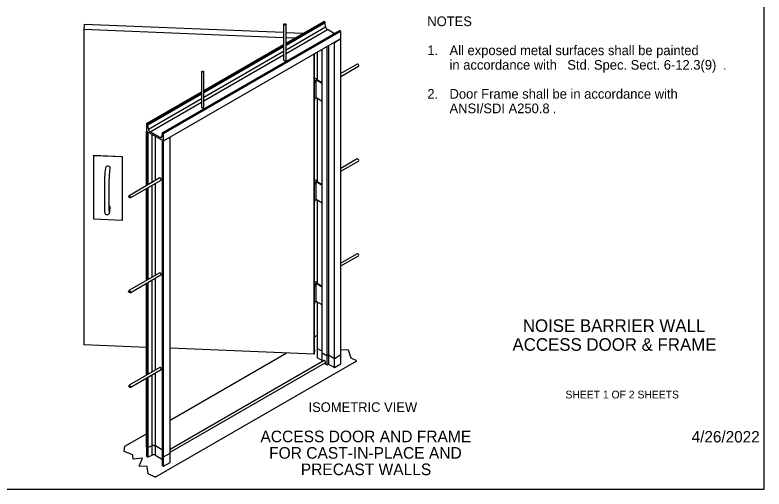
# Model space of a CAD drawing. Extents: x 99862 to 103151, y 100000 to 105076.
# Drawn here: x 101604 to 103151, y 100000 to 100979 of the extents above; entities that cross this region are included whole.
import ezdxf

# ---------------------------------------------------------------- set-up
doc = ezdxf.new("R2010")
doc.units = 0
for name, color, linetype in [('Level 1', 7, 'Continuous'), ('Level 15', 7, 'Continuous'), ('Level 18', 7, 'Continuous'), ('Level 20', 7, 'Continuous'), ('Level 5', 7, 'Continuous'), ('Level 62', 7, 'Continuous')]:
    doc.layers.add(name, color=color, linetype=linetype)

msp = doc.modelspace()

# ---------------------------------------------------------------- linework, layer by layer
at = {"layer": 'Level 1'}
msp.add_lwpolyline([(99862, 99999.5), (103151, 99999.5), (103151, 102075.5), (99862, 102075.5)], close=True, dxfattribs=at)
at = {"layer": 'Level 18'}
for p, q in [((101747.6, 100960), (101746.3, 100949.9)), ((102159.1, 100943), (101747.6, 100960)), ((102159.1, 100960), (102159.1, 100886.5)), ((102164.1, 100921.2), (102242.1, 100966.3)), ((102164.1, 100886.5), (102164.1, 100960)), ((102244.2, 100965.1), (102242.1, 100966.3)), ((102245.9, 100954.9), (102244.9, 100964)), ((101746.3, 100949.9), (102159.1, 100932.8)), ((101746.3, 100949.9), (101746.3, 100297.8)), ((101911.4, 100734.5), (102277.5, 100945.8)), ((102264.1, 100940.8), (102249.4, 100949.3)), ((102277.5, 100945.8), (102275.4, 100947)), ((101911.4, 100719.1), (102277.5, 100930.5)), ((102198.9, 100941.3), (102164.1, 100942.7)), ((102164.1, 100932.6), (102182.5, 100931.9)), ((102277.5, 100277.3), (102277.5, 100930.5)), ((101994.4, 100823.2), (102159.1, 100918.3)), ((102249.1, 100275.2), (102249.1, 100914.1)), ((102251.8, 100915.6), (102251.8, 100276.7)), ((102264.1, 100269.6), (102264.1, 100922.8)), ((102221.9, 100278), (102221.9, 100898.4)), ((102223.1, 100288.1), (102223.1, 100899.1)), ((102228.8, 100845.2), (102228.8, 100902.3)), ((102238.5, 100281.3), (102238.5, 100908)), ((102311.1, 100877.8), (102277.5, 100858.4)), ((102277.5, 100852.6), (102313.6, 100873.5)), ((101989.4, 100862.1), (101989.4, 100788.6)), ((101994.4, 100788.6), (101994.4, 100862.1)), ((102223.2, 100844.1), (102221.9, 100833.3)), ((102223.2, 100807.3), (102223.2, 100844.1)), ((102238.5, 100837.5), (102226.1, 100844.7)), ((102226.1, 100807.9), (102226.1, 100844.7)), ((102227.2, 100846.1), (102227.2, 100846.2)), ((102227.2, 100846.1), (102238.5, 100839.6)), ((101876, 100754.9), (101989.4, 100820.4)), ((102221.9, 100796.5), (102221.9, 100833.3)), ((102223.2, 100807.3), (102221.9, 100796.5)), ((102238.5, 100800.8), (102226.1, 100807.9)), ((102228.8, 100634.9), (102228.8, 100806.4)), ((101876, 100754.9), (101876, 100739.5)), ((101878.1, 100753.7), (101876, 100754.9)), ((101879.8, 100743.5), (101878.8, 100752.6)), ((101876, 100626.6), (101876, 100739.5)), ((101876, 100739.5), (101911.4, 100719.1)), ((101904.1, 100726), (101883.3, 100738)), ((101908.6, 100735.4), (101907.6, 100727.5)), ((101911.4, 100734.5), (101909.3, 100735.7)), ((101911.4, 100719.1), (101911.4, 100734.5)), ((101911.4, 100065.9), (101911.4, 100719.1)), ((101924.7, 100073.6), (101924.7, 100726.8)), ((101766.3, 100688.6), (101766.3, 100688.9)), ((101826.1, 100686.4), (101766.3, 100688.9)), ((101766.3, 100688.6), (101766.3, 100557.9)), ((101826.1, 100686.1), (101766.3, 100688.6)), ((101826.1, 100555.7), (101826.1, 100686.4)), ((101826.1, 100686.1), (101826.1, 100686.4)), ((101826.1, 100555.5), (101826.1, 100686.1)), ((102311.1, 100681.8), (102277.5, 100662.4)), ((102277.5, 100656.6), (102313.6, 100677.5)), ((101791.2, 100663.5), (101790.5, 100657.7)), ((101800.4, 100656.5), (101801.1, 100662.2)), ((101903.6, 100642.5), (101839.9, 100605.7)), ((101842.4, 100601.4), (101906.1, 100638.2)), ((102238.5, 100627.3), (102226.1, 100634.4)), ((102226.1, 100597.7), (102226.1, 100634.4)), ((102227.2, 100635.8), (102227.2, 100636)), ((102227.2, 100635.8), (102238.5, 100629.3)), ((101789, 100629.2), (101789, 100580.2)), ((101799, 100580.2), (101799, 100629.2)), ((101876, 100430.6), (101876, 100620.8)), ((102223.2, 100633.8), (102221.9, 100623)), ((102221.9, 100586.3), (102221.9, 100623)), ((102223.2, 100597.1), (102223.2, 100633.8)), ((102223.2, 100597.1), (102221.9, 100586.3)), ((102238.5, 100590.5), (102226.1, 100597.7)), ((102228.8, 100424.7), (102228.8, 100596.2)), ((101800.4, 100574.8), (101801.1, 100580.6)), ((101766.3, 100557.9), (101826.1, 100555.5)), ((101826.1, 100555.5), (101826.1, 100555.7)), ((102311.2, 100485.9), (102277.5, 100466.4)), ((102277.5, 100460.7), (102313.7, 100481.6)), ((101903.3, 100446.4), (101839.7, 100409.6)), ((101842.2, 100405.3), (101905.8, 100442.1)), ((101876, 100234.7), (101876, 100424.9)), ((102223.2, 100423.6), (102221.9, 100412.8)), ((102223.2, 100386.8), (102223.2, 100423.6)), ((102238.5, 100417), (102226.1, 100424.2)), ((102226.1, 100387.4), (102226.1, 100424.2)), ((102227.2, 100425.6), (102227.2, 100425.7)), ((102227.2, 100425.6), (102238.5, 100419.1)), ((102221.9, 100376), (102221.9, 100412.8)), ((102238.5, 100380.3), (102226.1, 100387.4)), ((102223.2, 100386.8), (102221.9, 100376)), ((102228.8, 100290), (102228.8, 100385.9)), ((101876, 100292.4), (101746.3, 100297.8)), ((102221.9, 100278), (101924.7, 100290.4)), ((102223.1, 100288.1), (102221.9, 100278)), ((102228.8, 100290), (102238.5, 100284.4)), ((102238.5, 100281.3), (102249.1, 100275.2)), ((102238.5, 100262.6), (102238.5, 100281.3)), ((102242.6, 100265), (101924.7, 100081.5)), ((102251.8, 100276.7), (102249.1, 100275.2)), ((102249.1, 100256.1), (102249.1, 100275.2)), ((102251.8, 100276.7), (102264.1, 100269.6)), ((102251.8, 100276.7), (102251.8, 100257.6)), ((102264.1, 100269.6), (102277.5, 100277.3)), ((102264.1, 100250.5), (102264.1, 100269.6)), ((102277.5, 100258.2), (102277.5, 100277.3)), ((101903.7, 100250.7), (101840.1, 100213.9)), ((101924.7, 100075.7), (102245.1, 100260.7)), ((102243.1, 100259.5), (102249.1, 100256.1)), ((102249.1, 100256.1), (102251.8, 100257.6)), ((102251.8, 100257.6), (102264.1, 100250.5)), ((102264.1, 100250.5), (102277.5, 100258.2)), ((101842.6, 100209.6), (101906.2, 100246.3)), ((101876, 100086.3), (101876, 100228.9)), ((101878.1, 100085.1), (101876, 100086.3)), ((101876, 100086.3), (101876, 100067.2)), ((101878.1, 100066.1), (101878.1, 100085.1)), ((101887.8, 100088.8), (101879.4, 100085.1)), ((101879.4, 100066), (101879.4, 100085.1)), ((101887.8, 100069.7), (101887.8, 100088.8)), ((101909.1, 100080), (101894.4, 100088.5)), ((101894.4, 100069.4), (101894.4, 100088.5)), ((101876, 100067.2), (101878.1, 100066.1)), ((101879.4, 100066), (101887.8, 100069.7)), ((101894.4, 100069.4), (101909.1, 100060.9)), ((101909.1, 100067.5), (101909.1, 100048.4)), ((101911.4, 100065.9), (101909.3, 100067.1)), ((101909.3, 100048), (101909.3, 100067.1)), ((101911.4, 100065.9), (101924.7, 100073.6)), ((101911.4, 100046.8), (101911.4, 100065.9)), ((101924.7, 100054.5), (101924.7, 100073.6)), ((101909.3, 100048), (101911.4, 100046.8)), ((101911.4, 100046.8), (101924.7, 100054.5))]:
    msp.add_line(p, q, dxfattribs=at)
msp.add_lwpolyline([(102238.5, 100265.3), (102228.8, 100270.9), (102228.8, 100290)], dxfattribs=at)
for centre, major_axis in [((102161.6, 100960), (-2.5, 0)), ((101991.9, 100862.1), (-2.5, 0)), ((101841.2, 100603.6), (-1.25, 2.17)), ((101840.9, 100407.5), (-1.25, 2.17)), ((101841.3, 100211.7), (-1.25, 2.17))]:
    msp.add_ellipse(centre, major_axis=major_axis, ratio=0.57735, dxfattribs=at)
for centre, major_axis, ratio, start_param, end_param in [((102244.2, 100964.3), (0.5, -0.866), 0.57735, 0.922861, 2.356194), ((102249.4, 100953.4), (-2.5, 4.33), 0.57735, 0.922861, 2.356194), ((102275.4, 100946.2), (-0.5, 0.866), 0.57735, 5.497787, 6.283223), ((102161.6, 100886.6), (-2.5, 0), 0.57735, 6.283185, 9.424778), ((102312.4, 100875.6), (-1.25, 2.17), 0.57735, 3.141593, 6.283185), ((102223.5, 100846.2), (3.75, 0), 0.57735, 6.227515, 7.949711), ((102223.5, 100846.2), (3.75, 0), 0.57735, 4.616659, 4.64064), ((102223.5, 100846.2), (3.75, 0), 0.57735, 4.64064, 5.497787), ((102223.5, 100846.2), (3.75, 0), 0.57735, 5.497787, 6.227515), ((102223.5, 100809.5), (3.75, 0), 0.57735, 4.64064, 5.497787), ((101991.9, 100788.7), (-2.5, 0), 0.57735, 0, 3.141593), ((101878.1, 100752.9), (0.5, -0.866), 0.57735, 0.922861, 2.356194), ((101883.3, 100742.1), (-2.5, 4.33), 0.57735, 0.922861, 2.356194), ((101904.1, 100730), (2.5, -4.33), 0.57735, 5.497792, 6.931121), ((101909.3, 100734.9), (-0.5, 0.866), 0.57735, 5.497787, 6.931121), ((102312.4, 100679.7), (-1.25, 2.17), 0.57735, 3.141593, 6.283185), ((101796.2, 100662.8), (4.96, -0.62), 0.814396, 0, 3.141568), ((101796.2, 100662.8), (4.96, -0.62), 0.814396, 3.141568, 3.141617), ((101904.8, 100640.3), (-1.25, 2.17), 0.57735, 3.141593, 6.283185), ((102223.5, 100636), (3.75, 0), 0.57735, 6.227515, 7.949711), ((102223.5, 100636), (3.75, 0), 0.57735, 4.64064, 5.497787), ((102223.5, 100636), (3.75, 0), 0.57735, 5.497787, 6.227515), ((101794, 100629.2), (5, 0), 0.57735, 6.211436, 6.283185), ((102223.5, 100636), (3.75, 0), 0.57735, 4.616659, 4.64064), ((102223.5, 100599.2), (3.75, 0), 0.57735, 4.64064, 5.497787), ((101794, 100580.2), (5, 0), 0.57735, 3.141593, 3.143635), ((101796.2, 100581.2), (4.96, -0.62), 0.814396, 6.283185, 7.346876), ((101795.5, 100575.4), (4.96, -0.62), 0.814396, 6.283185, 6.283208), ((102312.5, 100483.8), (-1.25, 2.17), 0.57735, 3.141593, 6.283185), ((101904.6, 100444.2), (-1.25, 2.17), 0.57735, 3.141569, 6.283185), ((102223.5, 100425.7), (3.75, 0), 0.57735, 6.227515, 7.949711), ((102223.5, 100425.7), (3.75, 0), 0.57735, 4.616659, 4.64064), ((102223.5, 100425.7), (3.75, 0), 0.57735, 4.64064, 5.497787), ((102223.5, 100425.7), (3.75, 0), 0.57735, 5.497787, 6.227515), ((102223.5, 100389), (3.75, 0), 0.57735, 4.64064, 5.497787), ((102243.9, 100262.8), (-1.25, 2.17), 0.57735, 3.141569, 6.283185), ((101904.8, 100248.4), (-1.25, 2.17), 0.57735, 3.141593, 6.283185), ((101878.8, 100085.5), (1, 0), 0.57735, 3.926991, 5.360325), ((101890.8, 100086.4), (-5, 0), 0.57735, 3.926991, 5.360325), ((101878.8, 100066.5), (1, 0), 0.57735, 3.926991, 5.360325), ((101890.8, 100067.4), (-5, 0), 0.57735, 3.926991, 5.360325), ((101910.1, 100048.4), (-1, 0), 0.57735, 6.283185, 7.068583)]:
    msp.add_ellipse(centre, major_axis=major_axis, ratio=ratio, start_param=start_param, end_param=end_param, dxfattribs=at)
for points in [[(101790.5, 100657.7), (101790.2, 100655.2), (101789.4, 100646.2), (101789, 100634.5), (101789, 100629.2)], [(101799, 100629.2), (101799, 100632.5), (101799.3, 100642.7), (101800, 100653), (101800.4, 100656.5)], [(101789, 100580.2), (101789, 100577.1), (101789.1, 100573.7), (101789.4, 100571.5), (101789.9, 100569.8), (101791.4, 100567.5), (101794.5, 100566.4), (101797.9, 100567.5), (101799.6, 100570.1), (101799.9, 100571.9), (101800.3, 100573.5), (101800.4, 100574.8)], [(101799.3, 100573.3), (101799.3, 100573.3), (101799.1, 100574.2), (101799, 100577.1), (101799, 100580.2)]]:
    msp.add_open_spline(points, degree=3, dxfattribs=at)
at = {"layer": 'Level 5'}
for p, q in [((102164.1, 100918.9), (102244.2, 100965.1)), ((102164.1, 100917.3), (102244.9, 100964)), ((102274.9, 100947.1), (101908.8, 100735.7)), ((101909.3, 100735.7), (102275.4, 100947)), ((102164.1, 100907.7), (102245.9, 100954.9)), ((102164.1, 100900.1), (102249.4, 100949.3)), ((102277.5, 100930.5), (102277.5, 100945.8)), ((102264.1, 100922.8), (102277.5, 100930.5)), ((101994.4, 100820.9), (102159.1, 100916)), ((101994.4, 100819.4), (102159.1, 100914.5)), ((101994.4, 100809.7), (102159.1, 100904.8)), ((101994.4, 100802.1), (102159.1, 100897.2)), ((101878.1, 100753.7), (101989.4, 100818)), ((101878.8, 100752.6), (101989.4, 100816.5)), ((101879.8, 100743.5), (101989.4, 100806.8)), ((101883.3, 100738), (101989.4, 100799.2)), ((101878.1, 100738.3), (101876, 100739.5)), ((101878.1, 100627.8), (101878.1, 100738.3)), ((101879.4, 100628.5), (101879.4, 100737.6)), ((101887.8, 100633.4), (101887.8, 100732.7)), ((101894.4, 100637.2), (101894.4, 100728.9)), ((101904.1, 100726), (101907.7, 100728)), ((101909.1, 100720.5), (101909.1, 100067.5)), ((101911.4, 100719.1), (101909.3, 100720.3)), ((101909.3, 100067.1), (101909.3, 100720.3)), ((101924.7, 100726.8), (101911.4, 100719.1)), ((101878.1, 100431.8), (101878.1, 100622)), ((101879.4, 100432.6), (101879.4, 100622.8)), ((101887.8, 100437.4), (101887.8, 100627.6)), ((101894.4, 100441.2), (101894.4, 100631.4)), ((101894.4, 100245.2), (101894.4, 100435.4)), ((101878.1, 100235.9), (101878.1, 100426.1)), ((101879.4, 100236.6), (101879.4, 100426.8)), ((101887.8, 100241.5), (101887.8, 100431.7)), ((102223.1, 100314.3), (102228.8, 100317.6)), ((101924.7, 100142), (102164.4, 100280.4)), ((101894.1, 100023.9), (102310.2, 100264.2)), ((101887.8, 100088.8), (101887.8, 100235.7)), ((101894.4, 100088.5), (101894.4, 100239.5)), ((101878.1, 100085.1), (101878.1, 100230.1)), ((101879.4, 100085.1), (101879.4, 100230.8)), ((101831.5, 100088.2), (101876, 100113.9))]:
    msp.add_line(p, q, dxfattribs=at)
for points in [[(102310.2, 100264.2), (102298.3, 100270.3), (102293.4, 100286.5), (102277.5, 100287.2)], [(101894.1, 100023.9), (101879.2, 100030.6), (101877.3, 100046.2), (101861.1, 100046.9), (101867.9, 100063.5), (101848.8, 100061.2), (101847.7, 100070), (101829.6, 100077.3), (101831.5, 100088.2)]]:
    msp.add_lwpolyline(points, dxfattribs=at)
msp.add_ellipse((101910.1, 100067.5), major_axis=(-1, 0), ratio=0.57735, start_param=6.283185, end_param=7.068583, dxfattribs=at)

# ---------------------------------------------------------------- texts
at = {"layer": 'Level 15'}
msp.add_text('4/26/2022', height=23.62, dxfattribs=at).set_placement((103001.6, 100095.8))
at = {"layer": 'Level 20'}
for s, height, p in [('NOTES', 20, (102455.8, 100956.4)), ('1.', 20, (102455.8, 100896.4)), ('All exposed metal surfaces shall be painted', 20, (102501.7, 100896.4)), ('in accordance with ', 20, (102501.7, 100866.4)), ('Std. Spec. Sect. 6-12.3(9)', 20, (102744.8, 100866.4)), ('.', 20, (103066.4, 100866.4)), ('2.', 20, (102455.8, 100806.4)), ('Door Frame shall be in accordance with', 20, (102501.7, 100806.4)), ('ANSI/SDI A250.8', 20, (102501.7, 100776.4)), ('.', 20, (102714.6, 100776.4)), ('ISOMETRIC VIEW', 20, (102210.5, 100158.8)), ('ACCESS DOOR AND FRAME', 24, (102111.3, 100096.2)), ('FOR CAST-IN-PLACE AND', 24, (102129.2, 100062.2)), ('PRECAST WALLS', 24, (102194.6, 100028.2))]:
    msp.add_text(s, height=height, dxfattribs=at).set_placement(p)
at = {"layer": 'Level 62'}
for s, height, p in [('NOISE BARRIER WALL', 26, (102653, 100324.3)), ('ACCESS DOOR & FRAME', 26, (102631.7, 100285.3)), ('SHEET 1 OF 2 SHEETS', 16, (102741.1, 100186.8))]:
    msp.add_text(s, height=height, dxfattribs=at).set_placement(p)

doc.saveas('drawing.dxf')
